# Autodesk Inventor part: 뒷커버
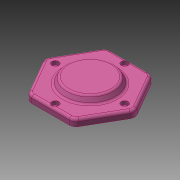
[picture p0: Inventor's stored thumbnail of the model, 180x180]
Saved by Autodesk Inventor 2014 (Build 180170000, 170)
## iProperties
Created: 2013-02
Part Number: 뒷커버
Document SubType Name: Modeling
Density: 1 g/cm^3
Material: 일반
Appearance: 분홍색
Author: 한국산업디자인학원[gmhk.co.kr]
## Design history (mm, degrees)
sketch "스케치1" dims "d37" = 105
  geometry: L1 (50.191, -4)-(28.559, -41.466); L2 (21.631, -45.466)-(-21.631, -45.466); L3 (-28.559, -41.466)-(-50.191, -4); L4 (-50.191, 4)-(-28.559, 41.466); L5 (-21.631, 45.466)-(21.631, 45.466); L6 (28.559, 41.466)-(50.191, 4); C1 r 30 at (0, 0); A1 r 8 centre (-21.631, 37.466) between (-21.631, 45.466) and (-28.559, 41.466); A2 r 8 centre (21.631, 37.466) between (28.559, 41.466) and (21.631, 45.466); A3 r 8 centre (43.262, 0) between (50.191, -4) and (50.191, 4); A4 r 8 centre (21.631, -37.466) between (21.631, -45.466) and (28.559, -41.466); A5 r 8 centre (-21.631, -37.466) between (-28.559, -41.466) and (-21.631, -45.466); A6 r 8 centre (-43.262, 0) between (-50.191, 4) and (-50.191, -4); 9 further points
  constraints: 12 end point, 12 point on circle, 12 point on line, 12 tangent, 7 centre point, 5 equal radius, 3 coincident, 1 horizontal, 1 horizontal alignment, 15 other
  dimensions: "d39" = 60 diameter of C1; "d40" = 8 radius of A1
extrude "돌출1" new body sketch "스케치1" distance "d0" = 8; taper "d1" = 0 deg
sketch "스케치2"
  geometry: C1 r 30 at (0, 0); 1 further point
  constraints: 1 centre point, 1 coincident
  dimensions: "d2" = 60 diameter of C1
extrude "돌출2" join sketch "스케치2" distance "d3" = 7; taper "d4" = -30 deg
sketch "스케치3"
  geometry: C1 r 30 at (0, 0) reference; A1 r 40 centre (0, 0) between (0, 40) and (-40, 0); 2 further points
  constraints: 4 point on circle, 2 horizontal alignment, 2 vertical alignment, 1 centre point, 1 coincident
  dimensions: "d47" = 80 diameter of A1
hole "구멍2" sketch "스케치3" at (0, 40), (-40, 0), (0, -40), (40, 0) diameter "d14" = 4.5; stored, may be unused: countersink angle "d18" = 90 deg, drill point angle "d20" = 118 deg; dims "d15" = 6, "d16" = 8, "d17" = 4.4, "d19" = 20
extrude "돌출3" join sketch "스케치1" distance "d21" = 12; taper "d22" = 0 deg
hole "구멍3" diameter "d25" = 30; stored, may be unused: countersink angle "d29" = 90 deg, drill point angle "d31" = 0 deg; dims "d26" = 6, "d27" = 42, "d28" = 13, "d30" = 16, "d50" = 10, "d51" = 10
fillet "모깎기1" dims "d32" = 3, "d33" = 1
chamfer "모따기1" distance "d34" = 1; stored, may be unused: second distance "d35" = 2, angle "d36" = 45 deg
chamfer "모따기2" distance "d43" = 1; stored, may be unused: second distance "d44" = 2, angle "d45" = 45 deg
fillet "모깎기2" dims "d46" = 3
node "솔리드1"
